// Mitsubishi GX Works2 project: 温度模块读取   PLC: FX3U/FX3UC

PROGRAM MAIN
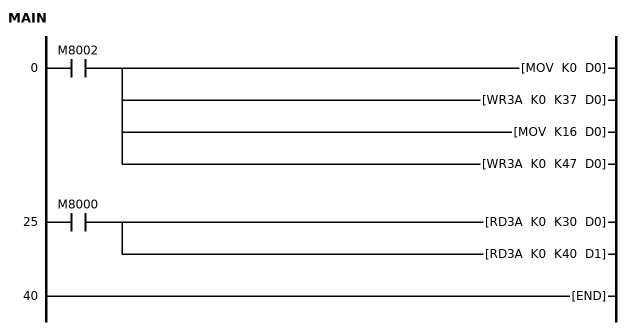
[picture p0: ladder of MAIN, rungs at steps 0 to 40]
0     LD      M8002
      MOV     K0 D0
      WR3A    K0 K37 D0
        [note] 设置通道0为Pt100
      MOV     K16 D0
      WR3A    K0 K47 D0
        [note] 设置通道1为K型热电偶
25    LD      M8000
      RD3A    K0 K30 D0
        [note] 读取通道0温度
      RD3A    K0 K40 D1
        [note] 读取通道1温度
40    END
END_PROGRAM
